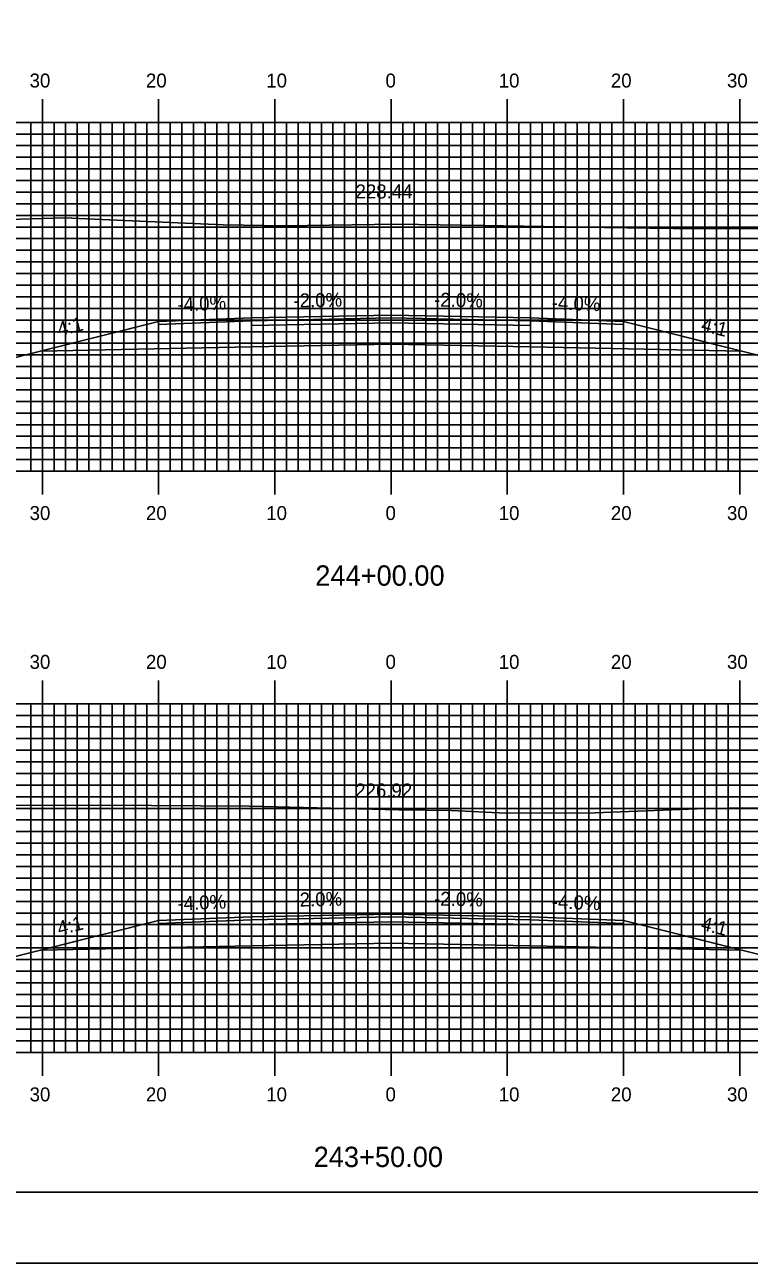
# Model space of a CAD drawing. Extents: x 1802716 to 1803060, y 442591 to 442811.
# Drawn here: x 1802850.6 to 1802912.9, y 442590.5 to 442697.1 of the extents above; entities that cross this region are included whole.
import ezdxf

# ---------------------------------------------------------------- set-up
doc = ezdxf.new("R2010")
doc.units = 0
for name, color, linetype in [('ANNOTATION', 7, 'Continuous'), ('BORDER', 7, 'Continuous'), ('D_Roadway_Centerline', 7, 'Continuous'), ('D_Roadway_Centerline_Text', 7, 'Continuous'), ('D_Roadway_Edge_Shoulder', 7, 'Continuous'), ('D_Roadway_Edge_TW', 7, 'Continuous'), ('D_Roadway_Pavement', 7, 'Continuous'), ('D_Roadway_SlopeLines', 7, 'Continuous'), ('D_Roadway_SubGrade', 7, 'Continuous'), ('H_V ANNOTATION', 7, 'Continuous'), ('MAJOR', 7, 'Continuous'), ('MINOR', 7, 'Continuous'), ('PLOT BOUNDARY', 7, 'Continuous'), ('S_Roadway_Centerline', 7, 'Continuous')]:
    doc.layers.add(name, color=color, linetype=linetype)

msp = doc.modelspace()

# ---------------------------------------------------------------- linework, layer by layer
at = {"layer": 'BORDER'}
msp.add_lwpolyline([(1802732.51, 442596.67), (1803052.51, 442596.67), (1803052.51, 442806.67), (1802732.51, 442806.67)], close=True, dxfattribs=at)
at = {"layer": 'D_Roadway_Centerline'}
for points in [[(1802798.76, 442679.66), (1802800.01, 442679.63), (1802801.26, 442679.51), (1802802.51, 442679.32), (1802803.76, 442679.04), (1802847.94, 442668), (1802851.94, 442669), (1802862.11, 442671.54), (1802870.11, 442671.86), (1802882.11, 442672.1), (1802894.11, 442671.86), (1802902.11, 442671.54), (1802912.29, 442669), (1802916.29, 442668), (1802960.6, 442679.08), (1802961.85, 442679.35), (1802963.1, 442679.55), (1802964.35, 442679.68), (1802965.6, 442679.72)], [(1802791.35, 442630), (1802792.6, 442629.96), (1802793.85, 442629.84), (1802795.1, 442629.65), (1802796.35, 442629.37), (1802847.94, 442616.48), (1802851.94, 442617.48), (1802862.11, 442620.02), (1802870.11, 442620.34), (1802882.11, 442620.58), (1802894.11, 442620.34), (1802902.11, 442620.02), (1802912.29, 442617.48), (1802916.29, 442616.48), (1802968.41, 442629.51), (1802969.66, 442629.78), (1802970.91, 442629.97), (1802972.16, 442630.08), (1802973.41, 442630.1)]]:
    msp.add_lwpolyline(points, dxfattribs=at)
at = {"layer": 'D_Roadway_Edge_Shoulder'}
for points in [[(1802870.11, 442671.86), (1802862.11, 442671.54), (1802862.11, 442671.29), (1802870.11, 442671.61)], [(1802894.11, 442671.86), (1802902.11, 442671.54), (1802902.11, 442671.29), (1802894.11, 442671.61)], [(1802870.11, 442620.34), (1802862.11, 442620.02), (1802862.11, 442619.77), (1802870.11, 442620.09)], [(1802894.11, 442620.34), (1802902.11, 442620.02), (1802902.11, 442619.77), (1802894.11, 442620.09)]]:
    msp.add_lwpolyline(points, close=True, dxfattribs=at)
at = {"layer": 'D_Roadway_Edge_TW'}
for points in [[(1802870.11, 442671.61), (1802870.11, 442671.86), (1802882.11, 442672.1), (1802894.11, 442671.86), (1802894.11, 442671.61), (1802882.11, 442671.85)], [(1802870.11, 442620.09), (1802870.11, 442620.34), (1802882.11, 442620.58), (1802894.11, 442620.34), (1802894.11, 442620.09), (1802882.11, 442620.33)]]:
    msp.add_lwpolyline(points, close=True, dxfattribs=at)
at = {"layer": 'D_Roadway_Pavement'}
for points in [[(1802870.11, 442671.2), (1802870.11, 442671.61), (1802882.11, 442671.85), (1802894.11, 442671.61), (1802894.11, 442671.2), (1802882.11, 442671.44)], [(1802870.11, 442619.67), (1802870.11, 442620.09), (1802882.11, 442620.33), (1802894.11, 442620.09), (1802894.11, 442619.67), (1802882.11, 442619.91)]]:
    msp.add_lwpolyline(points, close=True, dxfattribs=at)
at = {"layer": 'D_Roadway_SlopeLines'}
for points in [[(1802862.11, 442671.54), (1802847.94, 442668)], [(1802902.11, 442671.54), (1802916.29, 442668)], [(1802862.11, 442620.02), (1802847.94, 442616.48)], [(1802902.11, 442620.02), (1802916.29, 442616.48)]]:
    msp.add_lwpolyline(points, dxfattribs=at)
at = {"layer": 'D_Roadway_SubGrade'}
for points in [[(1802870.11, 442669.36), (1802851.94, 442669), (1802862.11, 442671.54), (1802862.11, 442671.29), (1802870.11, 442671.61), (1802882.11, 442671.85), (1802894.11, 442671.61), (1802902.11, 442671.29), (1802902.11, 442671.54), (1802912.29, 442669), (1802894.11, 442669.36), (1802882.11, 442669.6)], [(1802870.11, 442617.84), (1802851.94, 442617.48), (1802862.11, 442620.02), (1802862.11, 442619.77), (1802870.11, 442620.09), (1802882.11, 442620.33), (1802894.11, 442620.09), (1802902.11, 442619.77), (1802902.11, 442620.02), (1802912.29, 442617.48), (1802894.11, 442617.84), (1802882.11, 442618.08)]]:
    msp.add_lwpolyline(points, close=True, dxfattribs=at)
at = {"layer": 'MAJOR'}
for p, q in [((1802852.11, 442690.67), (1802852.11, 442688.67)), ((1802862.11, 442690.67), (1802862.11, 442688.67)), ((1802872.11, 442690.67), (1802872.11, 442688.67)), ((1802882.11, 442690.67), (1802882.11, 442688.67)), ((1802892.11, 442690.67), (1802892.11, 442688.67)), ((1802902.11, 442690.67), (1802902.11, 442688.67)), ((1802912.11, 442690.67), (1802912.11, 442688.67)), ((1802742.11, 442688.67), (1803022.11, 442688.67)), ((1802742.11, 442688.67), (1803022.11, 442688.67)), ((1802852.11, 442658.67), (1802852.11, 442688.67)), ((1802862.11, 442658.67), (1802862.11, 442688.67)), ((1802872.11, 442658.67), (1802872.11, 442688.67)), ((1802882.11, 442658.67), (1802882.11, 442688.67)), ((1802892.11, 442658.67), (1802892.11, 442688.67)), ((1802902.11, 442658.67), (1802902.11, 442688.67)), ((1802912.11, 442658.67), (1802912.11, 442688.67)), ((1802742.11, 442683.67), (1803022.11, 442683.67)), ((1802742.11, 442678.67), (1803022.11, 442678.67)), ((1802742.11, 442673.67), (1803022.11, 442673.67)), ((1802742.11, 442668.67), (1803022.11, 442668.67)), ((1802742.11, 442663.67), (1803022.11, 442663.67)), ((1802742.11, 442658.67), (1803022.11, 442658.67)), ((1802742.11, 442658.67), (1803022.11, 442658.67)), ((1802852.11, 442656.66), (1802852.11, 442658.67)), ((1802862.11, 442656.66), (1802862.11, 442658.67)), ((1802872.11, 442656.66), (1802872.11, 442658.67)), ((1802882.11, 442656.66), (1802882.11, 442658.67)), ((1802892.11, 442656.66), (1802892.11, 442658.67)), ((1802902.11, 442656.66), (1802902.11, 442658.67)), ((1802912.11, 442656.66), (1802912.11, 442658.67)), ((1802852.11, 442640.67), (1802852.11, 442638.67)), ((1802862.11, 442640.67), (1802862.11, 442638.67)), ((1802872.11, 442640.67), (1802872.11, 442638.67)), ((1802882.11, 442640.67), (1802882.11, 442638.67)), ((1802892.11, 442640.67), (1802892.11, 442638.67)), ((1802902.11, 442640.67), (1802902.11, 442638.67)), ((1802912.11, 442640.67), (1802912.11, 442638.67)), ((1802742.11, 442638.67), (1803022.11, 442638.67)), ((1802742.11, 442638.67), (1803022.11, 442638.67)), ((1802852.11, 442608.67), (1802852.11, 442638.67)), ((1802862.11, 442608.67), (1802862.11, 442638.67)), ((1802872.11, 442608.67), (1802872.11, 442638.67)), ((1802882.11, 442608.67), (1802882.11, 442638.67)), ((1802892.11, 442608.67), (1802892.11, 442638.67)), ((1802902.11, 442608.67), (1802902.11, 442638.67)), ((1802912.11, 442608.67), (1802912.11, 442638.67)), ((1802742.11, 442633.67), (1803022.11, 442633.67)), ((1802742.11, 442628.67), (1803022.11, 442628.67)), ((1802742.11, 442623.67), (1803022.11, 442623.67)), ((1802742.11, 442618.67), (1803022.11, 442618.67)), ((1802742.11, 442613.67), (1803022.11, 442613.67)), ((1802742.11, 442608.67), (1803022.11, 442608.67)), ((1802742.11, 442608.67), (1803022.11, 442608.67)), ((1802852.11, 442606.66), (1802852.11, 442608.67)), ((1802862.11, 442606.66), (1802862.11, 442608.67)), ((1802872.11, 442606.66), (1802872.11, 442608.67)), ((1802882.11, 442606.66), (1802882.11, 442608.67)), ((1802892.11, 442606.66), (1802892.11, 442608.67)), ((1802902.11, 442606.66), (1802902.11, 442608.67)), ((1802912.11, 442606.66), (1802912.11, 442608.67))]:
    msp.add_line(p, q, dxfattribs=at)
at = {"layer": 'MINOR'}
for p, q in [((1802851.11, 442658.67), (1802851.11, 442688.67)), ((1802853.11, 442658.67), (1802853.11, 442688.67)), ((1802854.11, 442658.67), (1802854.11, 442688.67)), ((1802855.11, 442658.67), (1802855.11, 442688.67)), ((1802856.11, 442658.67), (1802856.11, 442688.67)), ((1802857.11, 442658.67), (1802857.11, 442688.67)), ((1802858.11, 442658.67), (1802858.11, 442688.67)), ((1802859.11, 442658.67), (1802859.11, 442688.67)), ((1802860.11, 442658.67), (1802860.11, 442688.67)), ((1802861.11, 442658.67), (1802861.11, 442688.67)), ((1802863.11, 442658.67), (1802863.11, 442688.67)), ((1802864.11, 442658.67), (1802864.11, 442688.67)), ((1802865.11, 442658.67), (1802865.11, 442688.67)), ((1802866.11, 442658.67), (1802866.11, 442688.67)), ((1802867.11, 442658.67), (1802867.11, 442688.67)), ((1802868.11, 442658.67), (1802868.11, 442688.67)), ((1802869.11, 442658.67), (1802869.11, 442688.67)), ((1802870.11, 442658.67), (1802870.11, 442688.67)), ((1802871.11, 442658.67), (1802871.11, 442688.67)), ((1802873.11, 442658.67), (1802873.11, 442688.67)), ((1802874.11, 442658.67), (1802874.11, 442688.67)), ((1802875.11, 442658.67), (1802875.11, 442688.67)), ((1802876.11, 442658.67), (1802876.11, 442688.67)), ((1802877.11, 442658.67), (1802877.11, 442688.67)), ((1802878.11, 442658.67), (1802878.11, 442688.67)), ((1802879.11, 442658.67), (1802879.11, 442688.67)), ((1802880.11, 442658.67), (1802880.11, 442688.67)), ((1802881.11, 442658.67), (1802881.11, 442688.67)), ((1802883.11, 442658.67), (1802883.11, 442688.67)), ((1802884.11, 442658.67), (1802884.11, 442688.67)), ((1802885.11, 442658.67), (1802885.11, 442688.67)), ((1802886.11, 442658.67), (1802886.11, 442688.67)), ((1802887.11, 442658.67), (1802887.11, 442688.67)), ((1802888.11, 442658.67), (1802888.11, 442688.67)), ((1802889.11, 442658.67), (1802889.11, 442688.67)), ((1802890.11, 442658.67), (1802890.11, 442688.67)), ((1802891.11, 442658.67), (1802891.11, 442688.67)), ((1802893.11, 442658.67), (1802893.11, 442688.67)), ((1802894.11, 442658.67), (1802894.11, 442688.67)), ((1802895.11, 442658.67), (1802895.11, 442688.67)), ((1802896.11, 442658.67), (1802896.11, 442688.67)), ((1802897.11, 442658.67), (1802897.11, 442688.67)), ((1802898.11, 442658.67), (1802898.11, 442688.67)), ((1802899.11, 442658.67), (1802899.11, 442688.67)), ((1802900.11, 442658.67), (1802900.11, 442688.67)), ((1802901.11, 442658.67), (1802901.11, 442688.67)), ((1802903.11, 442658.67), (1802903.11, 442688.67)), ((1802904.11, 442658.67), (1802904.11, 442688.67)), ((1802905.11, 442658.67), (1802905.11, 442688.67)), ((1802906.11, 442658.67), (1802906.11, 442688.67)), ((1802907.11, 442658.67), (1802907.11, 442688.67)), ((1802908.11, 442658.67), (1802908.11, 442688.67)), ((1802909.11, 442658.67), (1802909.11, 442688.67)), ((1802910.11, 442658.67), (1802910.11, 442688.67)), ((1802911.11, 442658.67), (1802911.11, 442688.67)), ((1802742.11, 442687.67), (1803022.11, 442687.67)), ((1802742.11, 442686.67), (1803022.11, 442686.67)), ((1802742.11, 442685.67), (1803022.11, 442685.67)), ((1802742.11, 442684.67), (1803022.11, 442684.67)), ((1802742.11, 442682.67), (1803022.11, 442682.67)), ((1802742.11, 442681.67), (1803022.11, 442681.67)), ((1802742.11, 442680.67), (1803022.11, 442680.67)), ((1802742.11, 442679.67), (1803022.11, 442679.67)), ((1802742.11, 442677.67), (1803022.11, 442677.67)), ((1802742.11, 442676.67), (1803022.11, 442676.67)), ((1802742.11, 442675.67), (1803022.11, 442675.67)), ((1802742.11, 442674.67), (1803022.11, 442674.67)), ((1802742.11, 442672.67), (1803022.11, 442672.67)), ((1802742.11, 442671.67), (1803022.11, 442671.67)), ((1802742.11, 442670.67), (1803022.11, 442670.67)), ((1802742.11, 442669.67), (1803022.11, 442669.67)), ((1802742.11, 442667.67), (1803022.11, 442667.67)), ((1802742.11, 442666.67), (1803022.11, 442666.67)), ((1802742.11, 442665.67), (1803022.11, 442665.67)), ((1802742.11, 442664.67), (1803022.11, 442664.67)), ((1802742.11, 442662.67), (1803022.11, 442662.67)), ((1802742.11, 442661.67), (1803022.11, 442661.67)), ((1802742.11, 442660.67), (1803022.11, 442660.67)), ((1802742.11, 442659.67), (1803022.11, 442659.67)), ((1802742.11, 442637.67), (1803022.11, 442637.67)), ((1802851.11, 442608.67), (1802851.11, 442638.67)), ((1802853.11, 442608.67), (1802853.11, 442638.67)), ((1802854.11, 442608.67), (1802854.11, 442638.67)), ((1802855.11, 442608.67), (1802855.11, 442638.67)), ((1802856.11, 442608.67), (1802856.11, 442638.67)), ((1802857.11, 442608.67), (1802857.11, 442638.67)), ((1802858.11, 442608.67), (1802858.11, 442638.67)), ((1802859.11, 442608.67), (1802859.11, 442638.67)), ((1802860.11, 442608.67), (1802860.11, 442638.67)), ((1802861.11, 442608.67), (1802861.11, 442638.67)), ((1802863.11, 442608.67), (1802863.11, 442638.67)), ((1802864.11, 442608.67), (1802864.11, 442638.67)), ((1802865.11, 442608.67), (1802865.11, 442638.67)), ((1802866.11, 442608.67), (1802866.11, 442638.67)), ((1802867.11, 442608.67), (1802867.11, 442638.67)), ((1802868.11, 442608.67), (1802868.11, 442638.67)), ((1802869.11, 442608.67), (1802869.11, 442638.67)), ((1802870.11, 442608.67), (1802870.11, 442638.67)), ((1802871.11, 442608.67), (1802871.11, 442638.67)), ((1802873.11, 442608.67), (1802873.11, 442638.67)), ((1802874.11, 442608.67), (1802874.11, 442638.67)), ((1802875.11, 442608.67), (1802875.11, 442638.67)), ((1802876.11, 442608.67), (1802876.11, 442638.67)), ((1802877.11, 442608.67), (1802877.11, 442638.67)), ((1802878.11, 442608.67), (1802878.11, 442638.67)), ((1802879.11, 442608.67), (1802879.11, 442638.67)), ((1802880.11, 442608.67), (1802880.11, 442638.67)), ((1802881.11, 442608.67), (1802881.11, 442638.67)), ((1802883.11, 442608.67), (1802883.11, 442638.67)), ((1802884.11, 442608.67), (1802884.11, 442638.67)), ((1802885.11, 442608.67), (1802885.11, 442638.67)), ((1802886.11, 442608.67), (1802886.11, 442638.67)), ((1802887.11, 442608.67), (1802887.11, 442638.67)), ((1802888.11, 442608.67), (1802888.11, 442638.67)), ((1802889.11, 442608.67), (1802889.11, 442638.67)), ((1802890.11, 442608.67), (1802890.11, 442638.67)), ((1802891.11, 442608.67), (1802891.11, 442638.67)), ((1802893.11, 442608.67), (1802893.11, 442638.67)), ((1802894.11, 442608.67), (1802894.11, 442638.67)), ((1802895.11, 442608.67), (1802895.11, 442638.67)), ((1802896.11, 442608.67), (1802896.11, 442638.67)), ((1802897.11, 442608.67), (1802897.11, 442638.67)), ((1802898.11, 442608.67), (1802898.11, 442638.67)), ((1802899.11, 442608.67), (1802899.11, 442638.67)), ((1802900.11, 442608.67), (1802900.11, 442638.67)), ((1802901.11, 442608.67), (1802901.11, 442638.67)), ((1802903.11, 442608.67), (1802903.11, 442638.67)), ((1802904.11, 442608.67), (1802904.11, 442638.67)), ((1802905.11, 442608.67), (1802905.11, 442638.67)), ((1802906.11, 442608.67), (1802906.11, 442638.67)), ((1802907.11, 442608.67), (1802907.11, 442638.67)), ((1802908.11, 442608.67), (1802908.11, 442638.67)), ((1802909.11, 442608.67), (1802909.11, 442638.67)), ((1802910.11, 442608.67), (1802910.11, 442638.67)), ((1802911.11, 442608.67), (1802911.11, 442638.67)), ((1802742.11, 442636.67), (1803022.11, 442636.67)), ((1802742.11, 442635.67), (1803022.11, 442635.67)), ((1802742.11, 442634.67), (1803022.11, 442634.67)), ((1802742.11, 442632.67), (1803022.11, 442632.67)), ((1802742.11, 442631.67), (1803022.11, 442631.67)), ((1802742.11, 442630.67), (1803022.11, 442630.67)), ((1802742.11, 442629.67), (1803022.11, 442629.67)), ((1802742.11, 442627.67), (1803022.11, 442627.67)), ((1802742.11, 442626.67), (1803022.11, 442626.67)), ((1802742.11, 442625.67), (1803022.11, 442625.67)), ((1802742.11, 442624.67), (1803022.11, 442624.67)), ((1802742.11, 442622.67), (1803022.11, 442622.67)), ((1802742.11, 442621.67), (1803022.11, 442621.67)), ((1802742.11, 442620.67), (1803022.11, 442620.67)), ((1802742.11, 442619.67), (1803022.11, 442619.67)), ((1802742.11, 442617.67), (1803022.11, 442617.67)), ((1802742.11, 442616.67), (1803022.11, 442616.67)), ((1802742.11, 442615.67), (1803022.11, 442615.67)), ((1802742.11, 442614.67), (1803022.11, 442614.67)), ((1802742.11, 442612.67), (1803022.11, 442612.67)), ((1802742.11, 442611.67), (1803022.11, 442611.67)), ((1802742.11, 442610.67), (1803022.11, 442610.67)), ((1802742.11, 442609.67), (1803022.11, 442609.67))]:
    msp.add_line(p, q, dxfattribs=at)
at = {"layer": 'PLOT BOUNDARY'}
msp.add_lwpolyline([(1802716.33, 442590.55), (1803056.33, 442590.55), (1803056.33, 442810.55), (1802716.33, 442810.55)], close=True, dxfattribs=at)
at = {"layer": 'S_Roadway_Centerline'}
for points in [[(1802783.65, 442679.88), (1802796.84, 442679.67), (1802800.81, 442679.66), (1802804.41, 442679.75), (1802821.62, 442680.14), (1802826.92, 442680.14), (1802845.1, 442680.24), (1802846.8, 442680.25), (1802847.32, 442680.25), (1802853.97, 442680.45), (1802867.66, 442679.87), (1802872.98, 442679.77), (1802882.61, 442679.93), (1802890.06, 442679.8), (1802900.48, 442679.63), (1802906.38, 442679.54), (1802911.28, 442679.52), (1802917.62, 442679.58)], [(1802784.94, 442630.01), (1802794.27, 442630), (1802806.15, 442629.83), (1802806.17, 442629.83), (1802806.19, 442629.83), (1802811.07, 442630.01), (1802823.21, 442630.08), (1802827.43, 442630.03), (1802829.19, 442630.06), (1802831.5, 442630.02), (1802841.11, 442629.61), (1802849.45, 442629.92), (1802857.32, 442629.95), (1802869.9, 442629.85), (1802882.79, 442629.54), (1802887.31, 442629.49), (1802891.97, 442629.26), (1802899.68, 442629.28), (1802908.42, 442629.62), (1802912.36, 442629.71), (1802922.39, 442629.64)]]:
    msp.add_lwpolyline(points, dxfattribs=at)

# ---------------------------------------------------------------- texts
at = {"layer": 'ANNOTATION'}
for s, rotation, p in [('-2.0%', 1.1458, (1802873.72, 442672.74)), ('-2.0%', 358.8542, (1802885.8, 442672.83)), ('-4.0%', 2.2906, (1802863.75, 442672.41)), ('-4.0%', 357.7094, (1802895.91, 442672.59)), ('4:1', 14.0362, (1802853.56, 442670.27)), ('4:1', 345.9638, (1802908.71, 442670.76)), ('-4.0%', 2.2906, (1802863.75, 442620.89)), ('-2.0%', 1.1458, (1802873.72, 442621.21)), ('-2.0%', 358.8542, (1802885.8, 442621.31)), ('-4.0%', 357.7094, (1802895.91, 442621.07)), ('4:1', 14.0362, (1802853.56, 442618.74)), ('4:1', 345.9638, (1802908.71, 442619.23))]:
    msp.add_text(s, height=1.2, rotation=rotation, dxfattribs=at).set_placement(p)
at = {"layer": 'D_Roadway_Centerline'}
for s, p in [('C', (1802882.11, 442672.1)), ('L', (1802882.11, 442672.1)), ('C', (1802882.11, 442620.58)), ('L', (1802882.11, 442620.57))]:
    msp.add_text(s, height=0.0146, dxfattribs=at).set_placement(p)
at = {"layer": 'D_Roadway_Centerline_Text'}
for s, p in [('228.44', (1802879.05, 442682.13)), ('226.92', (1802879.02, 442630.61))]:
    msp.add_text(s, height=1.2, dxfattribs=at).set_placement(p)
at = {"layer": 'H_V ANNOTATION'}
for s, height, p in [('30', 1.2, (1802851.01, 442691.67)), ('20', 1.2, (1802861.02, 442691.67)), ('10', 1.2, (1802871.37, 442691.67)), ('0', 1.2, (1802881.63, 442691.67)), ('10', 1.2, (1802891.37, 442691.67)), ('20', 1.2, (1802901.02, 442691.67)), ('30', 1.2, (1802911.01, 442691.67)), ('30', 1.2, (1802851.01, 442654.47)), ('20', 1.2, (1802861.02, 442654.47)), ('10', 1.2, (1802871.37, 442654.47)), ('0', 1.2, (1802881.63, 442654.47)), ('10', 1.2, (1802891.37, 442654.47)), ('20', 1.2, (1802901.02, 442654.47)), ('30', 1.2, (1802911.01, 442654.47)), ('244+00.00', 1.75, (1802875.59, 442648.82)), ('30', 1.2, (1802851.01, 442641.67)), ('20', 1.2, (1802861.02, 442641.67)), ('10', 1.2, (1802871.37, 442641.67)), ('0', 1.2, (1802881.63, 442641.67)), ('10', 1.2, (1802891.37, 442641.67)), ('20', 1.2, (1802901.02, 442641.67)), ('30', 1.2, (1802911.01, 442641.67)), ('30', 1.2, (1802851.01, 442604.47)), ('20', 1.2, (1802861.02, 442604.47)), ('10', 1.2, (1802871.37, 442604.47)), ('0', 1.2, (1802881.63, 442604.47)), ('10', 1.2, (1802891.37, 442604.47)), ('20', 1.2, (1802901.02, 442604.47)), ('30', 1.2, (1802911.01, 442604.47)), ('243+50.00', 1.75, (1802875.45, 442598.82))]:
    msp.add_text(s, height=height, dxfattribs=at).set_placement(p)

doc.saveas('drawing.dxf')
